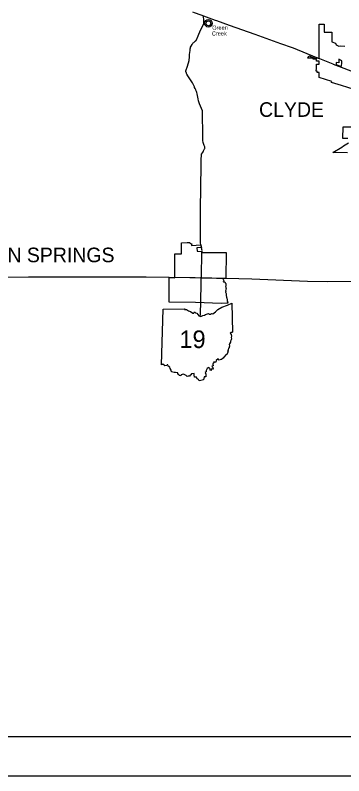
# Model space of a CAD drawing. Extents: x 0 to 798, y 0 to 440.
# Drawn here: x 368.1 to 452.7, y 0 to 195.7 of the extents above; entities that cross this region are included whole.
import ezdxf

# ---------------------------------------------------------------- set-up
doc = ezdxf.new("R2010")
doc.units = 0
for name, color, linetype in [('DV_X_Corp_Line', 7, 'Continuous'), ('GM_X_Corporation_Text', 7, 'Continuous'), ('GM_X_County', 7, 'Continuous'), ('GM_X_State_Route', 7, 'Continuous'), ('GM_X_US_Route', 7, 'Continuous'), ('PV_P_Text', 7, 'Continuous'), ('SH_Border', 7, 'Continuous'), ('SH_Cut_Line', 7, 'Continuous')]:
    doc.layers.add(name, color=color, linetype=linetype)

msp = doc.modelspace()

# ---------------------------------------------------------------- linework, layer by layer
at = {"layer": 'DV_X_Corp_Line'}
for points in [[(455.4, 176.59), (452.12, 177.62), (449.54, 178.4), (449.63, 178.63), (446.35, 179.66), (446.38, 180.98), (445.88, 180.99), (445.88, 181.29), (445.65, 181.29), (445.67, 182.04), (445.67, 182.12), (445.68, 183.09), (446.42, 183.09), (446.43, 183.85), (445.69, 183.86), (445.7, 184.33), (444.82, 184.35), (444.82, 184.6), (443.44, 184.62), (443.69, 185.27), (445.7, 184.45), (445.71, 184.84), (446.39, 184.57), (446.39, 193.39), (447.71, 193.38), (447.71, 191.33), (449.69, 191.31), (449.69, 188.83), (450.58, 188.54), (450.77, 188.03), (451.42, 187.7), (451.88, 187.78), (452.99, 187.74)], [(453.81, 163.94), (452.49, 163.96), (452.54, 166.98), (455.89, 166.96)], [(453.71, 160.29), (449.93, 160.37), (452.18, 161.76), (452.67, 162.06), (453.94, 162.83)]]:
    msp.add_lwpolyline(points, dxfattribs=at)
for points in [[(450.78, 182.99), (452.02, 182.51), (452.1, 182.79), (452.23, 183.23), (452.23, 183.98), (451.44, 184.36), (451.44, 183.48), (450.78, 183.52)], [(410.94, 134.28), (410.92, 137.15), (412.41, 137.2), (413, 137.22), (413.07, 137.16), (413.11, 137.08), (413.26, 136.95), (413.59, 136.86), (413.6, 136.78), (413.49, 136.57), (413.52, 136.42), (415.9, 136.57), (416.07, 135.9), (414.94, 135.84), (414.95, 134.94), (416.22, 134.89), (416.22, 134.6), (422.43, 134.68), (422.4, 127.91), (421.67, 127.83), (421.69, 127.73), (421.79, 127.59), (421.82, 127.41), (421.74, 127.25), (421.72, 127.19), (421.76, 127.12), (421.85, 127.06), (421.98, 127.12), (422.03, 127.11), (422.1, 126.97), (422.18, 126.92), (422.23, 126.81), (422.32, 126.71), (422.35, 126.63), (422.4, 126.47), (422.37, 126.25), (422.34, 125.98), (422.3, 125.86), (422.38, 125.73), (422.34, 125.62), (422.36, 125.53), (422.34, 125.46), (422.37, 125.4), (422.45, 125.38), (422.5, 125.29), (422.38, 125.24), (422.43, 125.11), (422.35, 125.05), (422.29, 124.86), (422.31, 124.84), (422.38, 124.78), (422.39, 124.72), (422.34, 124.58), (422.28, 124.52), (422.32, 124.39), (422.36, 124.33), (422.41, 124.17), (422.44, 124.1), (422.44, 124.05), (422.4, 123.94), (422.46, 123.88), (422.45, 123.82), (422.47, 123.79), (422.46, 123.58), (422.49, 123.51), (422.52, 123.31), (422.51, 123.24), (422.54, 123.17), (422.62, 122.86), (422.62, 122.79), (422.69, 122.65), (422.68, 122.46), (422.71, 122.33), (422.78, 122.07), (422.75, 121.97), (422.84, 121.67), (422.84, 121.58), (421.16, 121.55), (414.53, 121.8), (407.77, 121.84), (407.81, 128.19), (409.2, 128.15), (409.27, 134.31)]]:
    msp.add_lwpolyline(points, close=True, dxfattribs=at)
for radius in [0.982, 0.623]:
    msp.add_circle((417.88, 193.61), radius, dxfattribs=at)
at = {"layer": 'GM_X_County'}
msp.add_lwpolyline([(455.73, 127.16), (448.56, 127.13), (443.39, 127.19), (429.07, 127.74), (422.4, 127.91), (421.66, 127.93), (419.93, 127.97), (418.73, 128.01), (417.18, 128.04), (416.06, 128.07), (414.49, 128.09), (413.13, 128.12), (407.8, 128.23), (401.84, 128.32), (394.98, 128.31), (388.58, 128.32), (388.13, 128.32), (375.02, 128.26), (374.67, 128.27), (371.53, 128.26), (365.1, 128.22)], dxfattribs=at)
at = {"layer": 'GM_X_State_Route'}
for points in [[(414.78, 189.32), (414.78, 189.32), (415.22, 190.4), (415.87, 191.87), (416.43, 192.96), (416.69, 193.52), (416.69, 194.25), (416.69, 194.34), (416.65, 195.52)], [(416.18, 135.41), (416.15, 135.58), (416.11, 135.71), (416.07, 135.9), (415.9, 136.57), (415.88, 137.15), (415.81, 141.28), (415.85, 145.8), (415.99, 157.06), (416.02, 158.43), (416.07, 159.87), (416.08, 159.96), (416.32, 160.27), (416.52, 160.57), (416.65, 160.79), (416.74, 160.98), (416.9, 161.31), (416.93, 161.4), (416.95, 161.48), (416.96, 161.64), (416.96, 161.73), (416.95, 161.8), (416.82, 162.15), (416.54, 162.98), (416.43, 163.45), (416.41, 164.76), (416.34, 170.58), (416.34, 171.03), (416.33, 171.09), (415.62, 172.89), (415.33, 173.65), (415.21, 174.17), (414.97, 175.48), (414.9, 175.84), (414.8, 176.08), (414.65, 176.37), (414.61, 176.46), (414.55, 176.65), (414.47, 176.85), (414.34, 177.1), (414.27, 177.28), (414.19, 177.46), (414.04, 177.81), (413.77, 178.29), (412.58, 180.08), (412.36, 180.49), (412.26, 180.7), (412.2, 180.84), (412.18, 180.91), (412.15, 180.97), (412.12, 181.05), (412.11, 181.08), (412.1, 181.21), (412.1, 181.25), (412.1, 181.32), (412.09, 181.4), (412.47, 182.62), (412.9, 184.08), (413.02, 185), (413.05, 185.6), (413.15, 186.61), (413.19, 186.87), (413.19, 187), (413.2, 187.09), (413.23, 187.21), (413.24, 187.32), (413.26, 187.41), (413.3, 187.5), (413.44, 187.73), (413.73, 188.18), (413.91, 188.47), (413.98, 188.56), (414.13, 188.71), (414.29, 188.83), (414.41, 188.92), (414.53, 189.04), (414.59, 189.11), (414.68, 189.16), (414.72, 189.22), (414.78, 189.32)], [(416.22, 134.63), (416.22, 134.89), (416.23, 135.19), (416.19, 135.39), (416.18, 135.41)], [(415.87, 118.39), (416.09, 130.31), (416.11, 130.88), (416.15, 132.24), (416.16, 132.82), (416.17, 133.28), (416.18, 133.32)], [(416.18, 133.32), (416.22, 134.6), (416.22, 134.63)], [(416.06, 128.07), (416.07, 129.2), (416.09, 130.3)]]:
    msp.add_lwpolyline(points, dxfattribs=at)
at = {"layer": 'GM_X_US_Route'}
for points in [[(413.78, 196.58), (414.2, 196.42), (415.97, 195.77), (416.65, 195.52), (417.27, 195.29)], [(417.27, 195.29), (419.64, 194.45)], [(419.64, 194.45), (419.97, 194.33), (423.2, 193.17), (429.82, 190.79), (436.45, 188.37), (439.44, 187.35), (439.67, 187.26), (445.74, 184.83)], [(445.74, 184.83), (445.86, 184.78)], [(445.86, 184.78), (445.91, 184.76), (446.46, 184.54), (449.9, 183.15)], [(449.9, 183.15), (449.95, 183.13), (452.08, 182.28), (456.34, 180.71)]]:
    msp.add_lwpolyline(points, dxfattribs=at)
at = {"layer": 'PV_P_Text'}
msp.add_line((405.8, 105.71), (406.21, 120.07), dxfattribs=at)
msp.add_line((405.8, 105.71), (406.21, 120.07), dxfattribs=at)
for points in [[(406.21, 120.07), (411.78, 120.17), (411.69, 119.99), (412.22, 119.96), (412.78, 119.65), (413.25, 119.45), (413.83, 119), (414.17, 119), (414.32, 119.38), (414.58, 119.09), (414.9, 119.04), (415.44, 118.35), (415.89, 118.2), (416.43, 118.44), (416.83, 118.48), (417.12, 118.71), (417.88, 118.91), (418.1, 118.79), (418.5, 118.81), (418.71, 118.9), (419.06, 118.82), (419.68, 119.34), (420.32, 119.96), (421.31, 120.54), (422.78, 121.09), (423.94, 121.58), (424.11, 114.13)], [(406.21, 120.07), (411.78, 120.17), (411.69, 119.99), (412.22, 119.96), (412.78, 119.65), (413.25, 119.45), (413.83, 119), (414.17, 119), (414.32, 119.38), (414.58, 119.09), (414.9, 119.04), (415.44, 118.35), (415.89, 118.2), (416.43, 118.44), (416.83, 118.48), (417.12, 118.71), (417.88, 118.91), (418.1, 118.79), (418.5, 118.81), (418.71, 118.9), (419.06, 118.82), (419.68, 119.34), (420.32, 119.96), (421.31, 120.54), (422.78, 121.09), (423.94, 121.58), (424.11, 114.13)], [(424.11, 114.13), (423.93, 114.03), (423.67, 114.07), (423.49, 113.87), (423.71, 113.52), (423.81, 113.15), (423.72, 112.74), (423.81, 112.41), (423.75, 112.13), (423.58, 111.85), (423.53, 111.58), (423.38, 111.3), (423.39, 111.14), (423.26, 111.02), (423.28, 110.55), (423.21, 110.3), (423.24, 110.07), (423.02, 110.01), (423.07, 109.83), (422.93, 109.69), (422.96, 109.44), (422.8, 109.29), (422.95, 108.97), (422.83, 108.88), (422.73, 108.49), (422.44, 108.42), (421.88, 107.72), (421.68, 107.46), (421.45, 107.39), (421.33, 107.12), (421.05, 107.12), (420.63, 106.94), (420.36, 107.26), (419.89, 106.87), (419.83, 106.42), (419.23, 106.44), (419.26, 106.21), (419.12, 106.14), (419, 105.92), (419.07, 105.51), (418.79, 105.41), (418.83, 105.18), (419.01, 105.03), (419.09, 104.59), (418.79, 104.68), (418.54, 104.3), (418.29, 104.39), (418.37, 104.71), (417.95, 105.09), (417.55, 104.78), (417.34, 104.29), (417.34, 103.96), (417.04, 103.76), (417.23, 103.3), (417.19, 102.97), (417.2, 102.67), (416.82, 102.68), (416.6, 101.85)], [(424.11, 114.13), (423.93, 114.03), (423.67, 114.07), (423.49, 113.87), (423.71, 113.52), (423.81, 113.15), (423.72, 112.74), (423.81, 112.41), (423.75, 112.13), (423.58, 111.85), (423.53, 111.58), (423.38, 111.3), (423.39, 111.14), (423.26, 111.02), (423.28, 110.55), (423.21, 110.3), (423.24, 110.07), (423.02, 110.01), (423.07, 109.83), (422.93, 109.69), (422.96, 109.44), (422.8, 109.29), (422.95, 108.97), (422.83, 108.88), (422.73, 108.49), (422.44, 108.42), (421.88, 107.72), (421.68, 107.46), (421.45, 107.39), (421.33, 107.12), (421.05, 107.12), (420.63, 106.94), (420.36, 107.26), (419.89, 106.87), (419.83, 106.42), (419.23, 106.44), (419.26, 106.21), (419.12, 106.14), (419, 105.92), (419.07, 105.51), (418.79, 105.41), (418.83, 105.18), (419.01, 105.03), (419.09, 104.59), (418.79, 104.68), (418.54, 104.3), (418.29, 104.39), (418.37, 104.71), (417.95, 105.09), (417.55, 104.78), (417.34, 104.29), (417.34, 103.96), (417.04, 103.76), (417.23, 103.3), (417.19, 102.97), (417.2, 102.67), (416.82, 102.68), (416.6, 101.85)], [(416.6, 101.85), (415.95, 101.7), (415.5, 101.6), (415.34, 101.98), (415.01, 102.17), (414.8, 102.55), (414.34, 102.6), (414.23, 103.12), (414.18, 103.54), (413.55, 103.44), (413.37, 103.18), (413.15, 103.11), (413.02, 102.85), (412.71, 102.83), (412.38, 102.71), (412.17, 102.96), (411.63, 103.22), (411.38, 103.35), (410.88, 103.15), (410.77, 102.9), (410.37, 103.01), (410.27, 103.28), (410.03, 103.36), (409.97, 103.65), (409.45, 103.8), (409.05, 103.74), (408.35, 103.97), (408.31, 104.35), (408.07, 104.8), (407.94, 105.12), (407.5, 105.37), (407.41, 105.74), (407.27, 105.73), (407.14, 105.58), (406.64, 105.51), (406.45, 105.66), (406.17, 105.93), (405.8, 105.71)], [(416.6, 101.85), (415.95, 101.7), (415.5, 101.6), (415.34, 101.98), (415.01, 102.17), (414.8, 102.55), (414.34, 102.6), (414.23, 103.12), (414.18, 103.54), (413.55, 103.44), (413.37, 103.18), (413.15, 103.11), (413.02, 102.85), (412.71, 102.83), (412.38, 102.71), (412.17, 102.96), (411.63, 103.22), (411.38, 103.35), (410.88, 103.15), (410.77, 102.9), (410.37, 103.01), (410.27, 103.28), (410.03, 103.36), (409.97, 103.65), (409.45, 103.8), (409.05, 103.74), (408.35, 103.97), (408.31, 104.35), (408.07, 104.8), (407.94, 105.12), (407.5, 105.37), (407.41, 105.74), (407.27, 105.73), (407.14, 105.58), (406.64, 105.51), (406.45, 105.66), (406.17, 105.93), (405.8, 105.71)]]:
    msp.add_lwpolyline(points, dxfattribs=at)
at = {"layer": 'SH_Border'}
msp.add_lwpolyline([(30, 430), (670, 430), (670, 10), (30, 10)], close=True, dxfattribs=at)
at = {"layer": 'SH_Cut_Line'}
msp.add_lwpolyline([(0, 0), (680, 0), (680, 440), (0, 440)], close=True, dxfattribs=at)

# ---------------------------------------------------------------- texts
at = {"layer": 'DV_X_Corp_Line'}
for s, p in [('Green', (418.87, 191.97)), ('Creek', (418.76, 190.46))]:
    msp.add_text(s, height=1.042, rotation=0, dxfattribs=at).set_placement(p)
at = {"layer": 'GM_X_Corporation_Text'}
for s, p in [('CLYDE', (430.91, 169.54)), ('GREEN SPRINGS', (351.92, 132.14))]:
    msp.add_text(s, height=3.75, rotation=0, dxfattribs=at).set_placement(p)
at = {"layer": 'PV_P_Text'}
msp.add_text('19', height=4.528, dxfattribs=at).set_placement((410.43, 110.05))

doc.saveas('drawing.dxf')
